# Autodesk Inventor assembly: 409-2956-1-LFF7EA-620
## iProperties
Created: 2010-06
Part Number: 409-2956-1-LFF7EA-620
Document SubType Name: Assembly
Designer: S. Boerckel
Mass: 30630.3 g
Surface Area: 5981.15 cm^2
Volume: 3896.78 cm^3
Density: 7.8604 g/cm^3
Description: STRAINER MOUNT
Material: ASSEMBLY
SMR: =<Material>
Length: 26.250 in
Wide: 11.000 in
Thickness: 4.500 in
Author: S. Boerckel
Revision Number: 0
Subject: DEMIN WATER FORWARDING PUMP SKID-7EA
